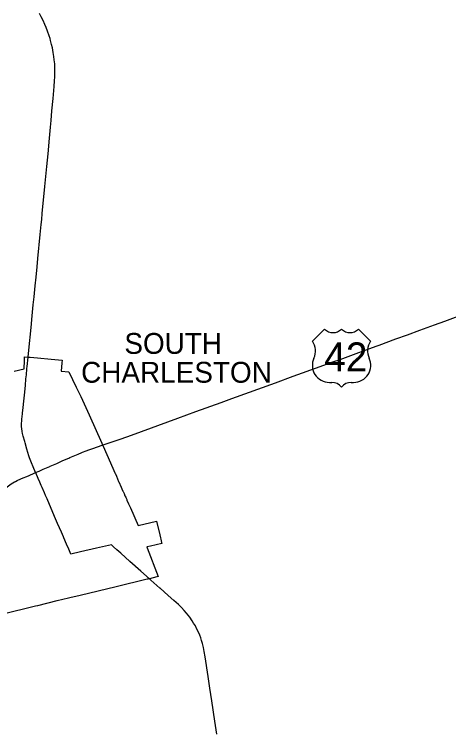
# Model space of a CAD drawing. Extents: x 0 to 34, y 0 to 22.
# Drawn here: x 7.8081 to 7.9754, y 15.4267 to 15.7021 of the extents above; entities that cross this region are included whole.
import ezdxf

# ---------------------------------------------------------------- set-up
doc = ezdxf.new("R2010")
doc.units = 0
for name, color, linetype in [('GM_X_Corporation', 7, 'Continuous'), ('GM_X_Corporation_Text', 7, 'Continuous'), ('GM_X_State_Route', 7, 'Continuous'), ('GM_X_US_Location', 7, 'Continuous'), ('GM_X_US_Route', 7, 'Continuous'), ('GM_X_US_Shield', 7, 'Continuous')]:
    doc.layers.add(name, color=color, linetype=linetype)

msp = doc.modelspace()

# ---------------------------------------------------------------- linework, layer by layer
at = {"layer": 'GM_X_Corporation'}
msp.add_lwpolyline([(7.807951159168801, 15.564454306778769), (7.811871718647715, 15.565407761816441), (7.811984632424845, 15.568645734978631), (7.8120339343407, 15.570057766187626), (7.813344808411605, 15.569938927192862), (7.813824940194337, 15.569895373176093), (7.8141663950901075, 15.569864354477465), (7.817026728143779, 15.569604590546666), (7.822301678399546, 15.569125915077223), (7.826474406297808, 15.568746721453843), (7.826369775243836, 15.567699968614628), (7.826054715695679, 15.564489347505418), (7.82912302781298, 15.564210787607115), (7.831882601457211, 15.558379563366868), (7.833624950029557, 15.554697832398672), (7.836959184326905, 15.547652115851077), (7.841743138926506, 15.536798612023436), (7.84206862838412, 15.536060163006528), (7.842263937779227, 15.535617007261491), (7.843694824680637, 15.532370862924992), (7.846889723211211, 15.525122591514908), (7.8469330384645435, 15.52502429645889), (7.846976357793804, 15.524926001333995), (7.847365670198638, 15.52404274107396), (7.848248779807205, 15.522038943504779), (7.848333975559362, 15.521845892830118), (7.849219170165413, 15.519837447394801), (7.849526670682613, 15.519139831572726), (7.849887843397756, 15.518320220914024), (7.849974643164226, 15.518123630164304), (7.850334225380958, 15.517307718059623), (7.850695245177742, 15.516488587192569), (7.8509611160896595, 15.515885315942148), (7.851132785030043, 15.515495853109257), (7.8513452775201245, 15.515013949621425), (7.851460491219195, 15.514752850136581), (7.852068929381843, 15.513372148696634), (7.852640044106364, 15.512076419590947), (7.852770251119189, 15.511780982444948), (7.855768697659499, 15.50497828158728), (7.862843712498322, 15.50663559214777), (7.86407752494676, 15.50144553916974), (7.864359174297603, 15.500260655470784), (7.864470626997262, 15.49979148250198), (7.864797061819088, 15.498419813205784), (7.86487089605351, 15.498106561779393), (7.860471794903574, 15.497100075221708), (7.859070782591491, 15.496774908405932), (7.859186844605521, 15.496471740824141), (7.863458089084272, 15.485309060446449), (7.860973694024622, 15.48471195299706), (7.860593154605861, 15.484620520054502), (7.860117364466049, 15.484506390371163), (7.859657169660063, 15.48439580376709), (7.859276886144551, 15.484304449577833), (7.8472823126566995, 15.481423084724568), (7.833372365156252, 15.478081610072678), (7.829416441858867, 15.477131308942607), (7.82894969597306, 15.477019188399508), (7.82451767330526, 15.475954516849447), (7.824502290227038, 15.47595083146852), (7.817027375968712, 15.47408929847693), (7.816237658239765, 15.473892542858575), (7.803266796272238, 15.470662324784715)], dxfattribs=at)
at = {"layer": 'GM_X_State_Route'}
msp.add_line((7.812562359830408, 15.561433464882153), (7.812666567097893, 15.562445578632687), dxfattribs=at)
for points in [[(7.821832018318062, 15.692686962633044), (7.821505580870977, 15.69375381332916), (7.820910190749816, 15.695496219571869), (7.820345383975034, 15.696969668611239), (7.819832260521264, 15.698179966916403), (7.8191698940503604, 15.699612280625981), (7.818459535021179, 15.7010219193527), (7.817704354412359, 15.702407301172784)], [(7.813393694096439, 15.569894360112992), (7.813653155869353, 15.572607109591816), (7.81454650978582, 15.581397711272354), (7.814978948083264, 15.585862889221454), (7.815369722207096, 15.590062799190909), (7.815702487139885, 15.593218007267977), (7.8158417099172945, 15.594535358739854), (7.816126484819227, 15.59742055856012), (7.816443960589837, 15.600736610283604), (7.816848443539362, 15.604685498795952), (7.817127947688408, 15.607880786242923), (7.818020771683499, 15.617159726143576), (7.8184147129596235, 15.621021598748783), (7.818602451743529, 15.62300131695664), (7.818816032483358, 15.625252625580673), (7.819834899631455, 15.63567541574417), (7.820560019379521, 15.643363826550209), (7.821038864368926, 15.648295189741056), (7.821578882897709, 15.65435880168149), (7.82197598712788, 15.658527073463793), (7.822223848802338, 15.661151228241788), (7.822569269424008, 15.664907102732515), (7.823030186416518, 15.66954261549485), (7.823453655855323, 15.674265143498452), (7.8236060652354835, 15.676365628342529), (7.8236756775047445, 15.677993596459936), (7.82368464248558, 15.6782055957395), (7.823708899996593, 15.680047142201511), (7.823687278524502, 15.681361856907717), (7.823607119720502, 15.682937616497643), (7.8234694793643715, 15.684509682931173), (7.823310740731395, 15.685814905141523), (7.823075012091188, 15.687375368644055), (7.822735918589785, 15.689185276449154), (7.8224463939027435, 15.69046729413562), (7.822040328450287, 15.691991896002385), (7.821832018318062, 15.692686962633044)], [(7.812666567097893, 15.562445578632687), (7.812718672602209, 15.562951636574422), (7.812947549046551, 15.56549246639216), (7.813031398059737, 15.566353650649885), (7.813393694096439, 15.569894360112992)], [(7.811242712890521, 15.548431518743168), (7.811438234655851, 15.550417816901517), (7.811574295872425, 15.551803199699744), (7.812076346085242, 15.556466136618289), (7.812327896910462, 15.559156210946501), (7.812562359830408, 15.561433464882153)], [(7.812196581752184, 15.53690416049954), (7.812076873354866, 15.537361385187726), (7.811458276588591, 15.539506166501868), (7.811211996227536, 15.540534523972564), (7.81106750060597, 15.541315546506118), (7.810937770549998, 15.542366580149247), (7.810889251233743, 15.543030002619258), (7.810862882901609, 15.543556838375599), (7.810862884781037, 15.544435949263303), (7.8109187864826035, 15.545259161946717), (7.8109883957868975, 15.545984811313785), (7.811097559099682, 15.547033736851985), (7.811209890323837, 15.54810850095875), (7.81122571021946, 15.548258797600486), (7.811242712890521, 15.548431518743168)], [(7.816274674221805, 15.525439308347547), (7.815300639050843, 15.527698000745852), (7.814655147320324, 15.529168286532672), (7.814144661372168, 15.53040125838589), (7.813858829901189, 15.531141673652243), (7.813610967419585, 15.5318958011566), (7.812892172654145, 15.534433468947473), (7.812196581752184, 15.53690416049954)], [(7.820653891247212, 15.515296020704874), (7.820077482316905, 15.516596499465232), (7.8196455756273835, 15.51756315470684), (7.818766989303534, 15.519629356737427), (7.818396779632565, 15.520478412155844), (7.817894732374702, 15.521673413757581), (7.817260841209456, 15.523143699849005), (7.816326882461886, 15.525315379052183), (7.816274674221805, 15.525439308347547)], [(7.829859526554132, 15.493974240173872), (7.829535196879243, 15.494671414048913), (7.828999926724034, 15.495865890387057), (7.828186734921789, 15.497834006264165), (7.827148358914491, 15.50026725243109), (7.826994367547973, 15.500621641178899), (7.826202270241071, 15.50245053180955), (7.824724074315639, 15.505847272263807), (7.823555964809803, 15.508514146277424), (7.820653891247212, 15.515296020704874)], [(7.845461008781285, 15.497593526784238), (7.842029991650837, 15.496775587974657), (7.839720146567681, 15.496235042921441), (7.833552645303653, 15.494842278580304), (7.829859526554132, 15.493974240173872)], [(7.86018496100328, 15.4844748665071), (7.856814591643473, 15.487391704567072), (7.852570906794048, 15.491180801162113), (7.84905920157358, 15.494302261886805), (7.847514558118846, 15.49567498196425), (7.846247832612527, 15.496822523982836), (7.845461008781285, 15.497593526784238)], [(7.864162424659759, 15.480873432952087), (7.8606870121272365, 15.48397281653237), (7.86018496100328, 15.4844748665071)], [(7.886050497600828, 15.424626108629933), (7.885329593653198, 15.429582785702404), (7.8841314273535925, 15.437398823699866), (7.883386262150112, 15.442328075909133), (7.882717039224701, 15.446810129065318), (7.881592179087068, 15.454339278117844), (7.881236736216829, 15.456415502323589), (7.880900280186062, 15.458022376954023), (7.88054694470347, 15.459494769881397), (7.880180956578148, 15.460757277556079), (7.87984661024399, 15.461753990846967), (7.879472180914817, 15.462735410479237), (7.878955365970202, 15.463944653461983), (7.878280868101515, 15.465371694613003), (7.877792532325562, 15.466301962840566), (7.877133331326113, 15.467438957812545), (7.876569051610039, 15.4683259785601), (7.875689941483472, 15.469637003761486), (7.875062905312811, 15.470479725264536), (7.874400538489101, 15.471294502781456), (7.873524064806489, 15.47227381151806), (7.872425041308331, 15.473408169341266), (7.871253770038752, 15.474529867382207), (7.869544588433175, 15.476084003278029), (7.8673692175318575, 15.478032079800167), (7.864225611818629, 15.480817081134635), (7.864162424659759, 15.480873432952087)]]:
    msp.add_lwpolyline(points, dxfattribs=at)
at = {"layer": 'GM_X_US_Route'}
msp.add_line((7.841931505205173, 15.535967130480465), (7.842091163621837, 15.536022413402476), dxfattribs=at)
for points in [[(7.842091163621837, 15.536022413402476), (7.843063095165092, 15.536347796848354), (7.849255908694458, 15.538468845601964), (7.853222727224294, 15.539895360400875), (7.871060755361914, 15.546390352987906), (7.877999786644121, 15.548908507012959), (7.887748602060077, 15.552447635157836), (7.891878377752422, 15.553945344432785), (7.908732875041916, 15.560058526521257), (7.915535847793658, 15.56252183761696), (7.925835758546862, 15.566261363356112), (7.93079190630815, 15.568062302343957), (7.933522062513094, 15.569038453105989), (7.939718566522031, 15.571289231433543), (7.943183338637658, 15.5725643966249), (7.94789215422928, 15.57427357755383), (7.94856876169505, 15.574522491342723), (7.955069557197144, 15.576909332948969), (7.959522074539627, 15.578551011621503), (7.964219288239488, 15.580292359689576), (7.969907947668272, 15.58239495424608), (7.973869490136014, 15.583843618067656), (7.979067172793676, 15.58575425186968)], [(7.834090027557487, 15.533149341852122), (7.834302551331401, 15.533238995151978), (7.835777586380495, 15.53381065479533), (7.836738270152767, 15.534153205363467)], [(7.836738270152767, 15.534153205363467), (7.838259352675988, 15.534695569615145), (7.841931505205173, 15.535967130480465)], [(7.816274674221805, 15.525439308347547), (7.817582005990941, 15.526000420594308), (7.8181541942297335, 15.526265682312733), (7.818656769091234, 15.526488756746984), (7.819201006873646, 15.526712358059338), (7.821727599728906, 15.527822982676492), (7.821932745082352, 15.527912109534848), (7.824383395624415, 15.528977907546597), (7.826793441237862, 15.530035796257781), (7.829021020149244, 15.531002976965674), (7.8294508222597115, 15.531189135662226), (7.832603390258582, 15.53252125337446), (7.834090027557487, 15.533149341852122)], [(7.799160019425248, 15.514882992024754), (7.801334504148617, 15.516656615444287), (7.8027483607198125, 15.517809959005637), (7.805813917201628, 15.520294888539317), (7.806864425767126, 15.521079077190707), (7.8075199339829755, 15.521506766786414), (7.808185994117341, 15.521871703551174), (7.808482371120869, 15.52201409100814), (7.809154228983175, 15.522331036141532), (7.810589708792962, 15.52297494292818), (7.810833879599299, 15.523084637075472), (7.813494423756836, 15.524224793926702), (7.815906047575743, 15.525278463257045), (7.816274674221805, 15.525439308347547)]]:
    msp.add_lwpolyline(points, dxfattribs=at)
at = {"layer": 'GM_X_US_Shield'}
for p, q in [((7.927580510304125, 15.580713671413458), (7.922918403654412, 15.576051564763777)), ((7.945296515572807, 15.576051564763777), (7.940634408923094, 15.580713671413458)), ((7.9294453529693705, 15.560200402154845), (7.930377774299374, 15.560200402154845)), ((7.937837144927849, 15.560200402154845), (7.938769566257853, 15.560200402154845))]:
    msp.add_line(p, q, dxfattribs=at)
for centre, radius, start, end in [((7.930843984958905, 15.584043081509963), 0.004662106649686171, 225.57299599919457, 314.4270040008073), ((7.937370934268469, 15.584043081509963), 0.004662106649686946, 225.57299599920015, 314.4270040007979), ((7.917571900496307, 15.572307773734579), 0.006526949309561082, 334.5471236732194, 35.000929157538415), ((7.950643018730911, 15.572307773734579), 0.006526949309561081, 144.99907084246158, 205.4528763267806), ((7.929372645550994, 15.566726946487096), 0.006526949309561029, 154.8319194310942, 270.63826363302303), ((7.938842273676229, 15.566726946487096), 0.006526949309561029, 269.36173636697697, 25.168080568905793), ((7.9303777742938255, 15.55553829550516), 0.0046621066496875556, 36.86989764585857, 89.99999993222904), ((7.937837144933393, 15.55553829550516), 0.0046621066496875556, 90.00000006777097, 143.13010235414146)]:
    msp.add_arc(centre, radius, start, end, dxfattribs=at)

# ---------------------------------------------------------------- texts
at = {"layer": 'GM_X_Corporation_Text'}
for s, p in [('SOUTH', (7.8504528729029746, 15.571183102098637)), ('CHARLESTON', (7.833796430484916, 15.560055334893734))]:
    msp.add_text(s, height=0.008037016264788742, rotation=1.0000000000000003e-05, dxfattribs=at).set_placement(p)
at = {"layer": 'GM_X_US_Location'}
for s, p in [('0', (7.934101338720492, 15.569902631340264)), ('/', (7.934102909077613, 15.569902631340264))]:
    msp.add_text(s, height=1.6074032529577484e-05, dxfattribs=at).set_placement(p)
msp.add_text('42', height=1.6074032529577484e-05, rotation=1.0000000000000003e-05, dxfattribs=at).set_placement((7.930783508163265, 15.56657534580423))
at = {"layer": 'GM_X_US_Shield'}
msp.add_text('42', height=0.011189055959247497, dxfattribs=at).set_placement((7.92742202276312, 15.56439629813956))

doc.saveas('drawing.dxf')
